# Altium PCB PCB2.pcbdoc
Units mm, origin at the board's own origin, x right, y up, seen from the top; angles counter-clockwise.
Board outline 115.73 x 193.8 mm, 2 copper layers (Top Layer, Bottom Layer); 58 components, 62 nets, 239 pads, 40 vias.
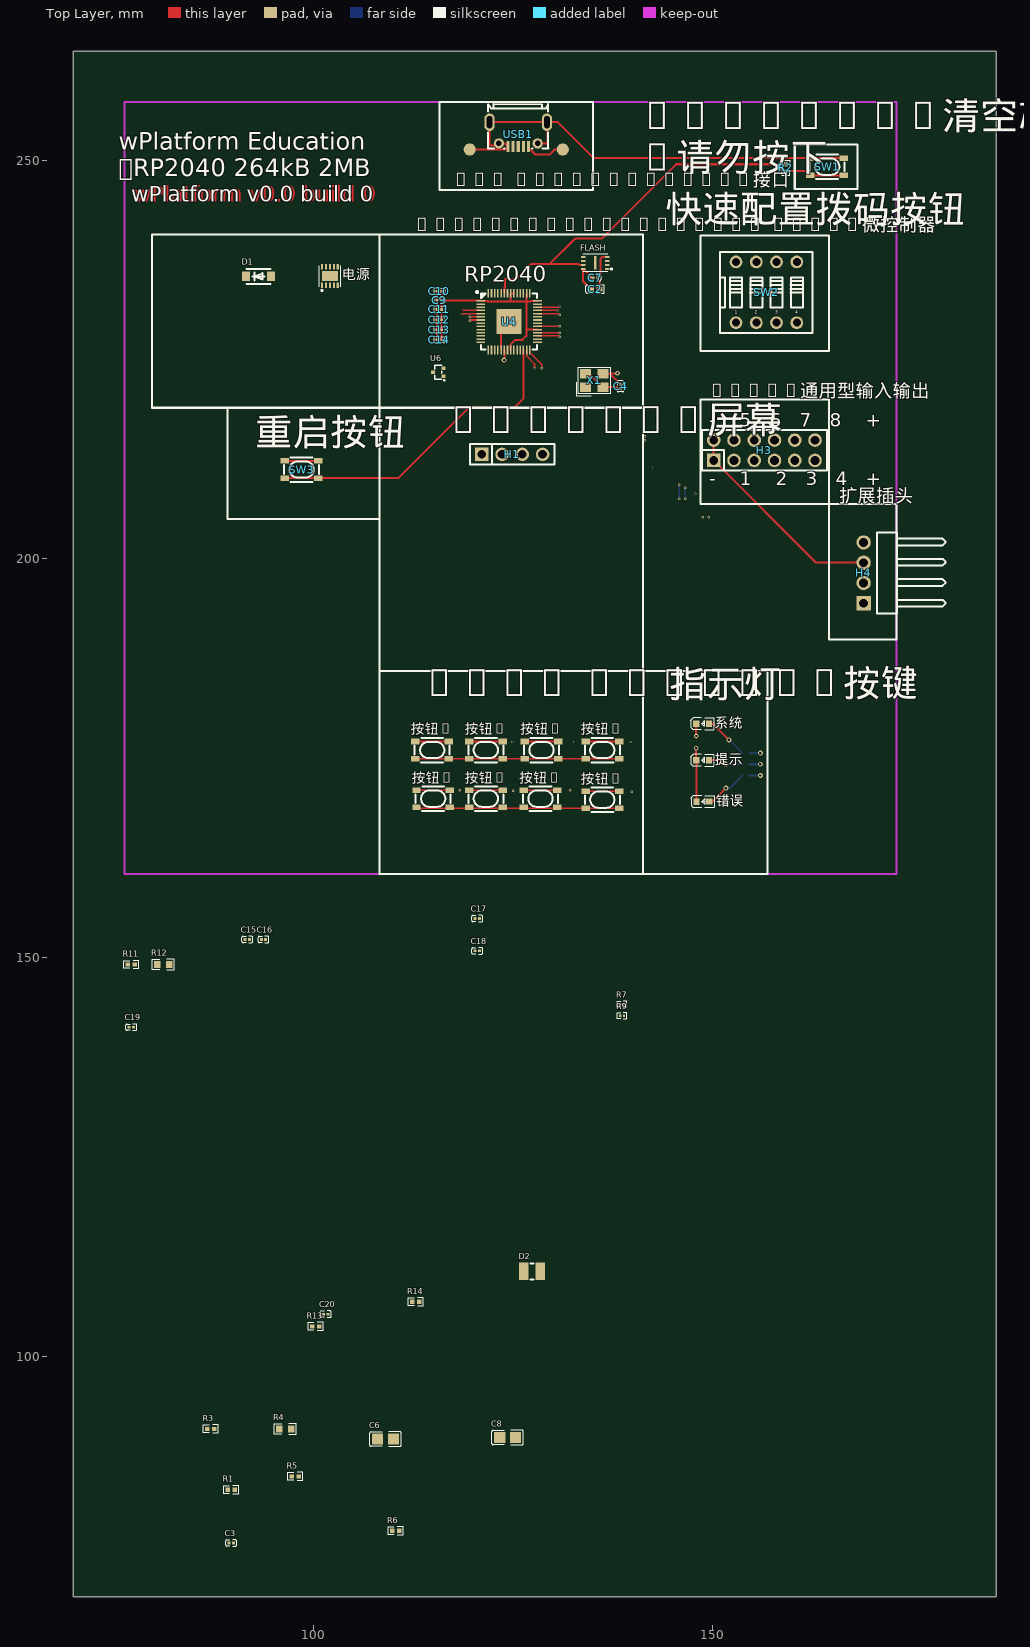
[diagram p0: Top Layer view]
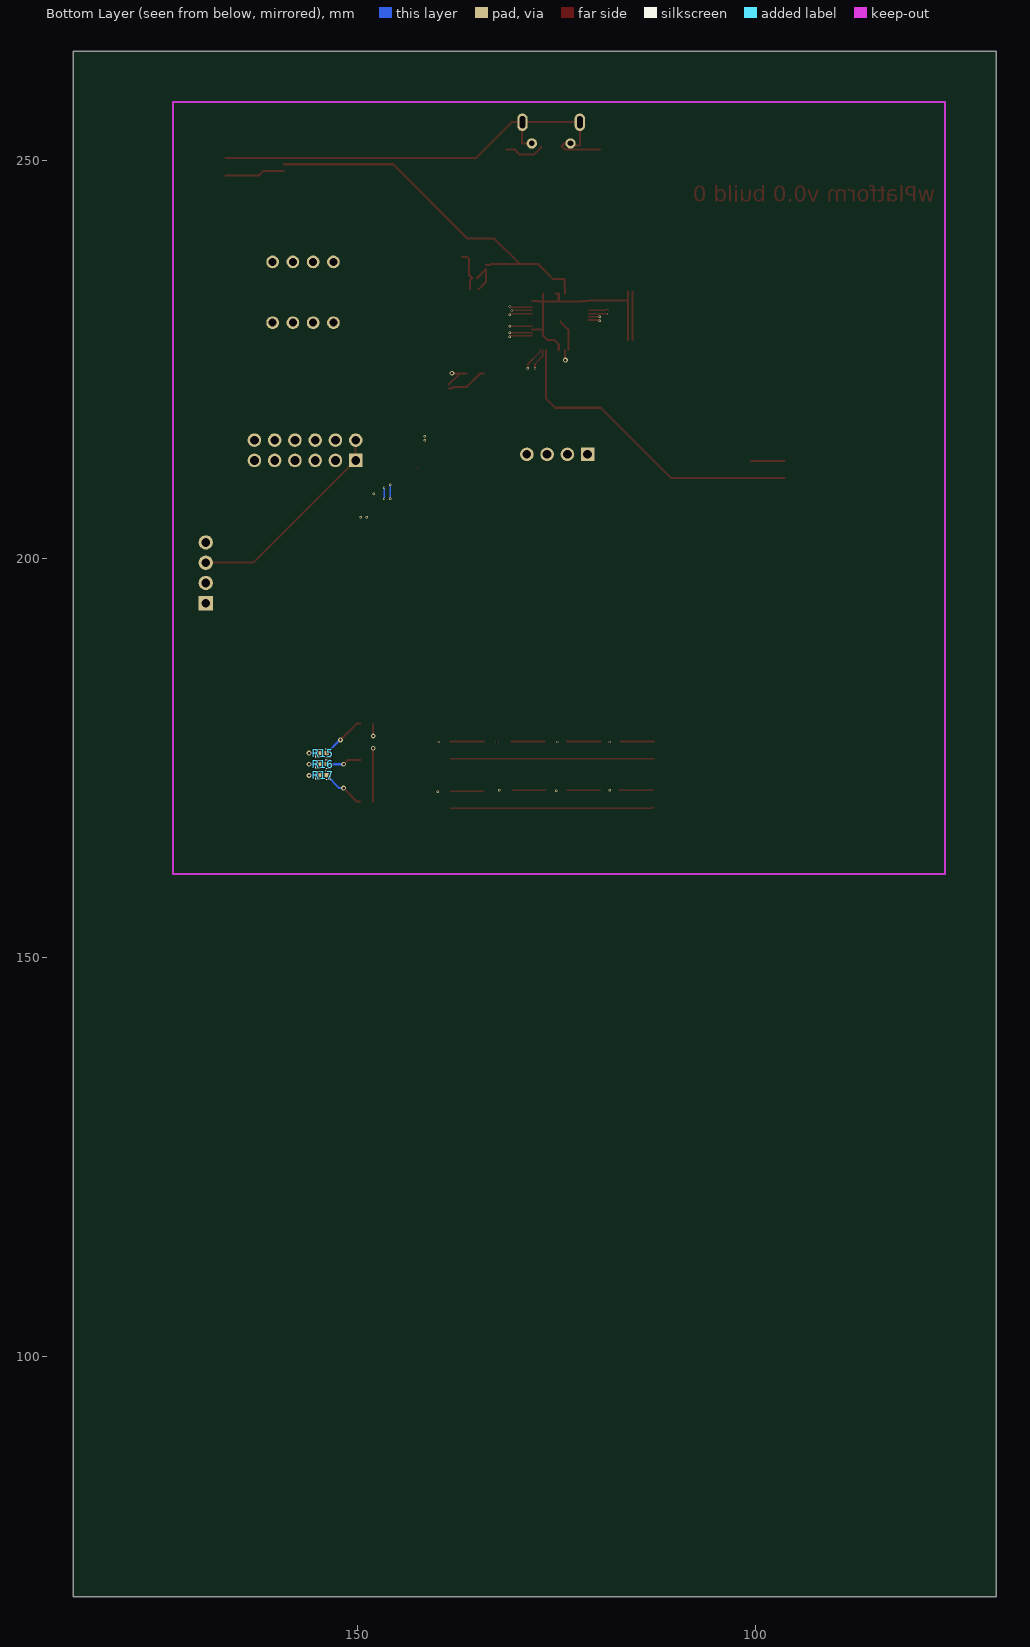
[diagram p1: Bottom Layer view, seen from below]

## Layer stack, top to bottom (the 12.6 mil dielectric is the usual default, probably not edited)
Top Layer: signal copper (thickness not stored)
Dielectric: dielectric 0.32, FR-4, Dk 4.8
Bottom Layer: signal copper (thickness not stored)

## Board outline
185.584,69.85 69.85,69.85 69.85,263.651 185.584,263.651

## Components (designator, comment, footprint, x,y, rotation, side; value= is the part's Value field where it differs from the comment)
C2 "CL05A225MQ5NSNC" C0402 135.298,233.823 r0 top
C3 "CL03C150JA3ANNC" C0201 89.655,76.591 r0 top
C4 "CL03C150JA3ANNC" C0201 138.481,221.614 r90 top
C6 "GRM21BR60J476ME01L" C0805 109.009,89.626 r0 top
C7 "GRM033R60J104KE19D" C0201 135.299,235.22 r180 top
C8 "GRM21BR60J476ME01L" C0805 124.32,89.816 r0 top
C9 "GRM033R60J104KE19D" C0201 115.748,232.409 r180 top
C10 "GRM033R60J104KE19D" C0201 115.748,233.552 r180 top
C11 "GRM033R60J104KE19D" C0201 115.748,231.266 r180 top
C12 "GRM033R60J104KE19D" C0201 115.748,229.996 r180 top
C13 "GRM033R60J104KE19D" C0201 115.748,228.726 r180 top
C14 "GRM033R60J104KE19D" C0201 115.748,227.456 r180 top
C15 "GRM033R60J104KE19D" C0201 91.682,152.268 r0 top
C16 "GRM033R60J104KE19D" C0201 93.708,152.268 r0 top
C17 "GRM033R60J104KE19D" C0201 120.509,154.897 r0 top
C18 "GRM033R60J104KE19D" C0201 120.509,150.834 r0 top
C19 "GRM033R60J104KE19D" C0201 77.144,141.267 r0 top
C20 "GRM033R71E102KA01D" C0201 101.514,105.293 r0 top
D1 "MBR120VLSFT1G" SOD-123F_L2.8-W1.8-LS3.7-RD 93.083,235.408 r0 top
D2 "SRN2512-2R2M" IND-SMD_L2.5-W2.0 127.396,110.644 r0 top
FLASH "W25Q16JVUXIQ" USON-8_L3.0-W2.0-P0.50-BL-EP 135.306,237.108 r90 top
H1 "2.54-1*4P母" HDR-TH_4P-P2.54-V-F 124.892,213.105 r0 top
H3 "B-2100S12P-B110" HDR-TH_12P-P2.54-V-M-R2-C6-S2.54 156.515,213.613 r0 top
H4 "2.54-1*4P反弯排针" HDR-TH_4P-P2.54-H-M-W10.4 168.961,198.246 r90 top
R1 "AECR0402F1K00K9" R0402 89.655,83.288 r0 top
R2 "AECR0402F1K00K9" R0402 159.182,249.046 r270 top
R3 "CR0402F5K60Q10Z" R0402 87.114,90.896 r0 top
R4 "0603WAF1002T5E" R0603 96.433,90.896 r0 top
R5 "RC0402FR-07100KL" R0402 97.703,84.937 r0 top
R6 "RC0402FR-07100KL" R0402 110.279,78.132 r0 top
R7 "RC0201FR-0727RL" R0201 138.667,144.134 r0 top
R9 "RC0201FR-0727RL" R0201 138.667,142.701 r0 top
R11 "RC0402FR-071RL" R0402 77.144,149.131 r0 top
R12 "RC0603FR-07200RL" R0603 81.139,149.131 r0 top
R13 "RC0402FR-07100KL" R0402 100.244,103.751 r0 top
R14 "RC0402FR-07200KL" R0402 112.82,106.835 r0 top
R15 "RC0402FR-07470RL" R0402 154.229,175.64 r180 bottom
R16 "RC0402FR-07470RL" R0402 154.229,174.243 r180 bottom
R17 "RC0402FR-07470RL" R0402 154.229,172.846 r180 bottom
SW1 "SKRPACE010" KEY-SMD_4P-L4.2-W3.2-P2.20-LS4.6 164.389,249.173 r0 top
SW2 "DS-04RP_C319060" SW-TH_DS-04XP 156.769,233.425 r0 top
SW3 "SKRPACE010" KEY-SMD_4P-L4.2-W3.2-P2.20-LS4.6 98.476,211.2 r0 top
U4 "RP2040_C2040" LQFN-56_L7.0-W7.0-P0.4-EP 124.503,229.749 r0 top
U6 "DMG1012T-13" SOT-523-3_L1.6-W0.8-P1.00-LS1.6-BR 115.621,223.392 r0 top
USB1 "MicroXNJ" MICRO-USB-SMD_MICROXNJ 125.654,253.237 r180 top
X1 "X322512MMB4SI" CRYSTAL-SMD_4P-L3.2-W2.5-BL 135.179,222.376 r0 top
按钮1 "SKRPACE010" KEY-SMD_4P-L4.2-W3.2-P2.20-LS4.6 114.859,176.021 r0 top
按钮2 "SKRPACE010" KEY-SMD_4P-L4.2-W3.2-P2.20-LS4.6 121.59,176.021 r0 top
按钮3 "SKRPACE010" KEY-SMD_4P-L4.2-W3.2-P2.20-LS4.6 128.575,176.021 r0 top
按钮4 "SKRPACE010" KEY-SMD_4P-L4.2-W3.2-P2.20-LS4.6 136.195,176.021 r0 top
按钮5 "SKRPACE010" KEY-SMD_4P-L4.2-W3.2-P2.20-LS4.6 114.986,169.925 r0 top
按钮6 "SKRPACE010" KEY-SMD_4P-L4.2-W3.2-P2.20-LS4.6 121.59,169.925 r0 top
按钮7 "SKRPACE010" KEY-SMD_4P-L4.2-W3.2-P2.20-LS4.6 128.448,169.925 r0 top
按钮8 "SKRPACE010" KEY-SMD_4P-L4.2-W3.2-P2.20-LS4.6 136.195,169.798 r0 top
提示 "19-217/GHC-YR1S2/3T" LED0603-RD 148.768,174.751 r0 top
电源 "RT6150BGQW" WSON-10_L2.5-W2.5-P0.50-BL-EP 102.032,235.457 r0 top
系统 "19-217/GHC-YR1S2/3T" LED0603-RD 148.768,179.323 r0 top
错误 "NCD0603R1_C84263" LED0603-RD_RED 148.81,169.563 r0 top

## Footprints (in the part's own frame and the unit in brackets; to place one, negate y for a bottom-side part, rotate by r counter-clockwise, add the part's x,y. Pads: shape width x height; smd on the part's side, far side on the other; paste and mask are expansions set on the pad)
C0201 [mm]
  rect 0.368x0.324 smd paste-100 mask+0.051: 1(-0.274,0) 2(0.274,0)
  silkscreen extent -0.69,-0.39 0.69,0.39
C0402 [mm]
  rect 0.79x0.54 smd paste-100 mask+0.051: 1(-0.545,0) 2(0.545,0)
  silkscreen extent -1.17,-0.5 1.17,0.5
C0805 [mm]
  rect 1.41x1.35 smd paste-100 mask+0.051: 1(-1,0) 2(1,0)
  silkscreen extent -1.96,-0.9 1.96,0.9
CRYSTAL-SMD_4P-L3.2-W2.5-BL [mm]
  rect 1.4x1.2 smd paste+0 mask+0.051: 1(-1.1,-0.85) 2(1.1,-0.85) 3(1.1,0.85) 4(-1.1,0.85)
  silkscreen extent -2.26,-1.91 2.03,1.68
HDR-TH_4P-P2.54-H-M-W10.4 [mm]
  rect 1.8x1.8 hole 1.1 mask+0.051: 1(-3.81,0)
  round 1.8 hole 1.1 mask+0.051: 2(-1.27,0) 3(1.27,0) 4(3.81,0)
  silkscreen extent -5.09,-10.27 5.07,-1.65
HDR-TH_4P-P2.54-V-F [mm]
  rect 1.7x1.7 hole 1.1 mask+0.051: 1(-3.81,0)
  round 1.7 hole 1.1 mask+0.051: 2(-1.27,0) 3(1.27,0) 4(3.81,0)
  silkscreen extent -5.29,-1.27 5.29,1.27
HDR-TH_12P-P2.54-V-M-R2-C6-S2.54 [mm]
  rect 1.7x1.7 hole 1.1 mask+0.051: 1(-6.35,-1.27)
  round 1.7 hole 1.1 mask+0.051: 2(-6.35,1.27) 3(-3.81,-1.27) 4(-3.81,1.27) 5(-1.27,-1.27) 6(-1.27,1.27) 7(1.27,-1.27) 8(1.27,1.27) 9(3.81,-1.27) 10(3.81,1.27) 11(6.35,-1.27) 12(6.35,1.27)
  silkscreen extent -7.85,-2.54 7.85,2.54
IND-SMD_L2.5-W2.0 [mm]
  rect 1.2x2.2 smd paste+0 mask+0.051: 1(1.028,0) 2(-1.028,0)
  silkscreen extent -0.2,-1.02 0.2,1.02
KEY-SMD_4P-L4.2-W3.2-P2.20-LS4.6 [mm]
  rect 1.05x0.7 smd mask+0.051: 1(-2.1,1.075) 2(2.1,1.075) 3(-2.1,-1.075) 4(2.1,-1.075)
  silkscreen extent -2.2,-1.55 2.2,1.52
LED0603-RD [mm]
  rect 0.8x0.8 smd paste+0 mask+0.051: 1(-0.799,-0.003) 2(0.799,0.003)
  silkscreen extent -1.49,-0.75 1.39,0.76
LED0603-RD_RED [mm]
  rect 0.8x0.8 smd mask+0.051: 1(-0.8,-0.003) 2(0.8,0.003)
  silkscreen extent -1.49,-0.75 1.39,0.76
LQFN-56_L7.0-W7.0-P0.4-EP [mm]
  rect 1.1x0.2 smd paste-100 mask+0.05: 1(-3.55,2.6) 2(-3.55,2.2) 3(-3.55,1.8) 4(-3.55,1.4) 5(-3.55,1) 6(-3.55,0.6) 7(-3.55,0.2) 8(-3.55,-0.2) 9(-3.55,-0.6) 10(-3.55,-1) 11(-3.55,-1.4) 12(-3.55,-1.8) 13(-3.55,-2.2) 14(-3.55,-2.6) 29(3.55,-2.6) 30(3.55,-2.2) 31(3.55,-1.8) 32(3.55,-1.4) 33(3.55,-1) 34(3.55,-0.6) 35(3.55,-0.2) 36(3.55,0.2) 37(3.55,0.6) 38(3.55,1) 39(3.55,1.4) 40(3.55,1.8) 41(3.55,2.2) 42(3.55,2.6)
  rect 0.2x1.1 smd paste-100 mask+0.05: 15(-2.6,-3.55) 16(-2.2,-3.55) 17(-1.8,-3.55) 18(-1.4,-3.55) 19(-1,-3.55) 20(-0.6,-3.55) 21(-0.2,-3.55) 22(0.2,-3.55) 23(0.6,-3.55) 24(1,-3.55) 25(1.4,-3.55) 26(1.8,-3.55) 27(2.2,-3.55) 28(2.6,-3.55) 43(2.6,3.55) 44(2.2,3.55) 45(1.8,3.55) 46(1.4,3.55) 47(1,3.55) 48(0.6,3.55) 49(0.2,3.55) 50(-0.2,3.55) 51(-0.6,3.55) 52(-1,3.55) 53(-1.4,3.55) 54(-1.8,3.55) 55(-2.2,3.55) 56(-2.6,3.55)
  rect 3.1x3.1 smd paste-100 mask+0.05: 57(0,0)
  silkscreen extent -4.13,-3.5 3.5,3.83
MICRO-USB-SMD_MICROXNJ [mm]
  rect 0.4x1.4 smd paste-100 mask+0.051: 1(-1.3,1.521) 2(-0.65,1.521) 3(0,1.521) 4(0.65,1.521) 5(1.3,1.521)
  round 1.3 hole 0.7 mask+0.051: 6(2.425,1.149) 9(-2.425,1.149)
  oval 1.3x2.2 hole 0.7 slot 1.5 at 90 deg mask+0.051: 7(3.6,-1.521) 8(-3.6,-1.521)
  silkscreen extent -3.76,-3.78 3.8,1.79
R0201 [mm]
  rect 0.303x0.324 smd paste-100 mask+0.051: 1(-0.242,0) 2(0.242,0)
  silkscreen extent -0.62,-0.39 0.62,0.39
R0402 [mm]
  rect 0.566x0.54 smd paste-100 mask+0.051: 1(-0.433,0) 2(0.433,0)
  silkscreen extent -0.94,-0.5 0.94,0.5
R0603 [mm]
  rect 0.806x0.864 smd paste-100 mask+0.051: 1(-0.753,0) 2(0.753,0)
  silkscreen extent -1.39,-0.66 1.39,0.66
SOD-123F_L2.8-W1.8-LS3.7-RD [mm]
  rect 1x1.2 smd paste+0 mask+0.051: 1(-1.55,0) 2(1.55,0)
  silkscreen extent -1.52,-0.93 1.49,0.95
SOT-523-3_L1.6-W0.8-P1.00-LS1.6-BR [mm]
  rect 0.51x0.4 smd paste+0 mask+0.051: 1(0.65,-0.5) 2(0.65,0.5) 3(-0.65,0)
  silkscreen extent -0.45,-1.08 0.83,0.9
SW-TH_DS-04XP [mm]
  round 1.6 hole 1 mask+0.051: 1(-3.81,-3.81) 2(-1.27,-3.81) 3(1.27,-3.81) 4(3.81,-3.81) 5(3.81,3.81) 6(1.27,3.81) 7(-1.27,3.81) 8(-3.81,3.81)
  silkscreen extent -5.83,-5.11 5.79,5.05
USON-8_L3.0-W2.0-P0.50-BL-EP [mm]
  rect 0.28x0.6 smd paste+0 mask+0.051: 1(-0.75,-1.507) 2(-0.25,-1.507) 3(0.25,-1.507) 4(0.75,-1.507) 5(0.75,1.507) 6(0.25,1.507) 7(-0.25,1.507) 8(-0.75,1.507)
  rect 1.7x0.3 smd paste+0 mask+0.051: 9(0,0)
  silkscreen extent -1.08,-2.13 1.08,1.58
WSON-10_L2.5-W2.5-P0.50-BL-EP [mm]
  rect 0.28x0.665 smd paste+0 mask+0.051: 1(-1,-1.157) 2(-0.5,-1.157) 3(0,-1.157) 4(0.5,-1.157) 5(1,-1.157) 6(1,1.157) 7(0.5,1.157) 8(0,1.157) 9(-0.5,1.157) 10(-1,1.157)
  rect 2x1.25 smd paste+0 mask+0.051: 11(0,0)
  silkscreen extent -1.33,-1.89 1.33,1.33

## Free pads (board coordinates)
  round 1.524 smd mask+0.051: 1(131.242,251.332) 2(119.558,251.332)

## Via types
v1: diameter 0.3, hole 0.2, Top Layer to Bottom Layer, 28 vias
v2: diameter 0.61, hole 0.305, Top Layer to Bottom Layer, 10 vias
v3: diameter 0.2, hole 0.15, Top Layer to Bottom Layer, 2 vias

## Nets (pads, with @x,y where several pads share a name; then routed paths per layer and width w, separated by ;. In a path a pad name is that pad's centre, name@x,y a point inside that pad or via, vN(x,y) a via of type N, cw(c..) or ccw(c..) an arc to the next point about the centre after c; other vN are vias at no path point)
0GPIO23: R6.2 U4.35 电源.7
0GPIO24: R3.1 R4.1 U4.36
0USB0: R7.1 U4.47
0USB1: R9.1 U4.46
1V10: C15.2 C16.1 C18.2 U4.23 U4.45 U4.50
$1N2633: C6.2 D1.1 R5.2 R14.2 电源.5 电源.8
$1N2647: R5.1 电源.6
$1N2652: D2.1 电源.4
$1N2653: D2.2 电源.2
$1N2694: C3.2 R1.1 X1.1
$1N2712: SW2.1 U4.8
$1N2715: SW2.2 U4.9
$1N2718: SW2.3 U4.11
$1N2721: SW2.4 U4.12
$1N2886: R11.2 R12.2 U4.43
$1N2892: C19.2 R11.1
$1N2897: U4.41 U6.2
$1N2936: C20.2 R13.2 R14.1 U6.3
$1N3176: R2.2 SW1.3 SW1.4 | length 7.5
  Top Layer w0.254: R2.2 161.774,248.613 SW1.3 SW1.4
$1N4076: R7.2 USB1.3
$1N4082: R9.2 USB1.2
$1N6993: R15.2 系统.2 | length 5.8
  Top Layer w0.254: 系统.2 150.034,179.326 v2(152.07,177.291)
  Bottom Layer w0.254: v2(152.07,177.291) 152.081,177.302 152.134,177.302 R15.2
$1N7116: R16.2 提示.2 | length 4.4
  Top Layer w0.254: 提示.2 151.177,174.754 v2(151.689,174.243)
  Bottom Layer w0.254: v2(151.689,174.243) R16.2
$1N7152: R17.2 错误.2 | length 5.5
  Top Layer w0.254: 错误.2 150,169.567 v2(151.689,171.256)
  Bottom Layer w0.254: v2(151.689,171.256) 152.206,171.256 R17.2
BOOTSEL_TO_EEPROM: FLASH.7 R2.1 U4.51 | length 47.2
  Top Layer w0.254: U4.51 123.903,234.026 124.003,234.126 124.003,235.076 125.4,235.076 127.305,236.981 129.591,236.981 ; FLASH.7 133.321,236.858 133.198,236.981 129.591,236.981 ; R2.1 145.466,249.479 136.143,240.156 132.766,240.156 129.591,236.981
EPCLK0: FLASH.6 U4.52
EPSD00: FLASH.5 U4.53
EPSD10: FLASH.2 U4.55
EPSD20: FLASH.3 U4.54
EPSS0: FLASH.1 U4.56
GND: C2.2 C3.1 C4.1 C6.1 C7.1 C8.2 C9.2 C10.2 C11.2 C12.2 C13.2 C14.2 C15.1 C16.2 C17.1 C18.1 C19.1 C20.1 FLASH.4 H1.1 H3.1 H3.2 H4.3 pad.2 R4.2 R6.1 R13.1 SW1.1 SW1.2 SW3.1 SW3.2 U4.19 U4.57 USB1.5 USB1.6 USB1.7 USB1.8 USB1.9 X1.2 X1.4 提示.1 电源.3 电源.9 电源.11 系统.1 错误.1 | length 121.5
  Top Layer w0.254: SW3.1 SW3.2 ; C14.2 C13.2 C12.2 C11.2 C9.2 C10.2 ; pad.2 123.97,251.332 USB1.5 123.981,252.088 USB1.6 122.981,251.84 122.054,251.84 USB1.7 USB1.8 USB1.8@129.337,254.675 ; U4.19 123.503,228.749 U4.57 ; USB1.9 129.337,252.088 USB1.8@129.337,254.675 ; X1.4 134.579,223.226 X1.2 137.955,221.526 138.141,221.34 C4.1 ; C2.2 135.843,234.951 C7.1 135.941,235.588 135.941,237.616 136.183,237.858 FLASH.4 ; v2(147.968,176.246) 提示.1 148.011,174.705 错误.1 ; v2(147.968,177.787) 系统.1 ; H3.2 H3.1 162.992,199.516 H4.3 ; SW1.2 SW1.1 135.12,250.248 130.607,254.761 129.423,254.761 USB1.8@129.337,254.675
  Inner1 w0.254: v2(147.968,176.246) v2(147.968,177.787)
GP0: H3.3 U4.31 | length 42.5
  Top Layer w0.2: U4.31 130.749,227.949 v1(130.861,227.837)
  Inner2 w0.2: v1(130.861,227.837) 131.75,226.948 135.052,226.948 136.195,225.805 139.37,225.805 142.037,223.138 142.037,209.295 142.926,208.406 146.736,208.406 147.371,209.041 149.403,209.041 H3.3
GP1: H3.5 U4.32 | length 45.1
  Top Layer w0.2: U4.32 130.853,228.349 v1(130.861,228.341)
  Inner1 w0.2: v1(142.418,211.454) 142.418,209.93 144.196,208.152 v1(147.879,208.152)
  Inner2 w0.2: v1(130.861,228.341) 130.992,228.341 132.004,227.329 135.179,227.329 136.322,226.186 139.57,226.186 142.418,223.338 v1(142.418,211.454) ; v1(147.879,208.152) 150.673,208.152 154.864,212.343 H3.5
GP2: H3.7 U4.34 | length 49.6
  Top Layer w0.2: U4.34 130.856,229.149 v1(130.861,229.144)
  Inner2 w0.2: v1(130.861,229.144) 132.295,227.71 135.306,227.71 136.449,226.567 139.751,226.567 142.799,223.519 142.799,211.781 143.053,211.527 143.053,211.327 142.799,211.073 142.799,210.057 143.942,208.914 v1(146.609,208.914) ; v1(146.609,207.517) 147.879,207.517 148.133,207.771 153.213,207.771 H3.7
  Bottom Layer w0.2: v1(146.609,207.517) v1(146.609,208.914)
GP3: H3.9 U4.5 | length 65.4
  Top Layer w0.2: v3(118.542,230.758) 120.944,230.758 U4.5
  Inner2 w0.2: v3(118.542,230.758) 126.67,230.758 127.813,229.615 130.988,229.615 132.385,228.218 135.052,228.218 135.258,228.012 135.431,228.012 136.574,226.869 139.876,226.869 143.101,223.644 143.101,211.914 143.688,211.327 143.307,210.946 143.307,210.184 144.196,209.295 v1(145.847,209.295) ; v1(145.847,207.517) 146.355,207.009 146.863,207.009 146.99,207.136 148.26,207.136 148.514,207.39 155.372,207.39 H3.9
  Bottom Layer w0.2: v1(145.847,207.517) v1(145.847,209.295)
GP4: H3.4 U4.38 | length 31.2
  Top Layer w0.2: U4.38 130.743,230.749 v1(130.861,230.631)
  Inner2 w0.2: v1(130.861,230.631) 132.893,228.599 135.306,228.599 136.703,227.202 140.386,227.202 H3.4
GP5: H3.6 U4.39 | length 33.9
  Top Layer w0.2: U4.39 130.607,231.149 v1(130.607,231.139)
  Inner2 w0.2: v1(130.607,231.139) 131.242,231.139 133.401,228.98 135.56,228.98 136.957,227.583 140.513,227.583 152.07,216.026 154.102,216.026 H3.6
GP6: H3.8 U4.40 | length 36.7
  Top Layer w0.2: U4.40 130.763,231.549 v1(130.861,231.647)
  Inner2 w0.2: v1(130.861,231.647) 131.242,231.647 133.528,229.361 135.687,229.361 137.084,227.964 140.64,227.964 152.197,216.407 156.261,216.407 H3.8
GP7: H3.10 U4.4 | length 51.8
  Top Layer w0.2: v3(118.574,231.149) U4.4
  Inner2 w0.2: v3(118.574,231.149) 129.22,231.149 130.353,232.282 131.623,232.282 134.163,229.742 135.814,229.742 137.211,228.345 140.767,228.345 152.324,216.788 158.42,216.788 H3.10
IOVDD00: C2.1 C7.2 C8.1 C9.1 C10.1 C11.1 C12.1 C13.1 C14.1 C17.2 FLASH.8 H1.2 H3.11 H3.12 R12.1 SW2.5 SW2.6 SW2.7 SW2.8 U4.1 U4.10 U4.22 U4.33 U4.42 U4.44 U4.48 U4.49 U6.1 按钮1.3 按钮1.4 按钮2.3 按钮2.4 按钮3.3 按钮3.4 按钮4.3 按钮4.4 按钮5.3 按钮5.4 按钮6.3 按钮6.4 按钮7.3 按钮7.4 按钮8.3 按钮8.4 电源.1 电源.10 | length 95.3
  Top Layer w0.2: 按钮1.3 按钮1.4 按钮2.3 按钮2.4 按钮3.3 按钮3.4 按钮4.3 按钮4.4 ; 按钮5.3 113.013,168.723 按钮8.3 按钮8.4
  Top Layer w0.254: C14.1 C13.1 C12.1 C11.1 C9.1 ; C10.1 C9.1 ; U4.22 124.703,226.886 125.273,227.456 126.162,227.456 126.67,227.964 126.67,228.622 ; U4.48 U4.49 124.703,232.282 ; U4.44 126.703,232.282 ; U4.33 126.797,228.749 126.67,228.622 ; U4.42 127.326,232.349 127.259,232.282 126.703,232.282 ; C2.1 133.798,234.778 FLASH.8 134.936,235.22 C7.2 ; C9.1 120.893,232.409 U4.1 121.68,232.349 121.747,232.282 124.703,232.282 ; 124.703,232.282 126.703,232.282 ; 126.67,228.622 126.67,232.249 126.703,232.282
  Inner1 w0.254: SW2.8 SW2.7 SW2.6 SW2.5
  Inner2 w0.2: H3.11 H3.12
LED0: R16.1 U4.2 | length 5.1
  Inner2 w0.254: v2(156.007,174.245) 156.515,174.245 156.642,174.372 156.642,177.418
  Bottom Layer w0.254: R16.1 156.005,174.243 v2(156.007,174.245)
LED1: R17.1 U4.3 | length 6.5
  Inner2 w0.254: v2(156.007,172.836) 157.277,174.106 157.277,177.418
  Bottom Layer w0.254: R17.1 155.997,172.846 v2(156.007,172.836)
OBLED: R15.1 U4.37 | length 3.1
  Inner2 w0.254: v2(156.007,175.64) 156.007,177.418
  Bottom Layer w0.254: R15.1 v2(156.007,175.64)
RUN: SW3.3 SW3.4 U4.26 | length 40.2
  Top Layer w0.254: SW3.3 SW3.4 110.609,210.125 119.431,218.947 125.146,218.947 126.289,220.09 126.289,226.185 U4.26
SCL: H1.3 U4.6 | length 24.8
  Top Layer w0.2: v1(119.558,230.377) 120.925,230.377 U4.6
  Inner1 w0.2: v1(119.558,230.377) 119.308,230.377 118.415,229.484 118.415,228.726 118.288,228.599 118.288,217.296 120.828,214.756 124.511,214.756 H1.3
SDA: H1.4 U4.7 | length 25.8
  Top Layer w0.2: v1(119.558,229.869) 119.638,229.949 U4.7
  Inner1 w0.2: v1(119.558,229.869) 118.796,229.107 118.796,217.55 121.209,215.137 126.67,215.137 H1.4
SWCLK: U4.24
SWD: U4.25
UARTRX: H4.2 U4.28 | length 56.8
  Top Layer w0.2: U4.28 127.103,225.88 128.575,224.408 v1(128.575,223.9)
  Inner1 w0.2: v1(141.529,215.391) 143.688,215.391 149.53,209.549 v1(149.53,205.231)
  Inner2 w0.2: v1(128.575,223.9) 137.084,215.391 141.377,215.391 ; v1(149.53,205.231) 157.785,196.976 H4.2
UARTTX: H4.1 U4.27 | length 58.7
  Top Layer w0.2: U4.27 126.703,225.424 127.686,224.441 v1(127.686,223.9)
  Inner1 w0.2: v1(141.529,214.883) 143.434,214.883 148.768,209.549 v1(148.768,205.231)
  Inner2 w0.2: v1(127.686,223.9) 136.576,215.01 141.152,215.01 141.279,214.883 v1(141.529,214.883) ; v1(148.768,205.231) 157.404,196.595 166.802,196.595 H4.1
UB0: U4.13 按钮1.1 按钮1.2 | length 4.2
  Top Layer w0.2: 按钮1.1 按钮1.2
  other v1: 118.288,177.037
UB1: U4.14 按钮5.1 按钮5.2 | length 4.2
  Top Layer w0.2: 按钮5.1 按钮5.2
UB2: U4.15 按钮2.1 按钮2.2 | length 4.2
  Top Layer w0.254: 按钮2.1 按钮2.2
  other v1: 124.892,177.037
UB3: U4.16 按钮6.1 按钮6.2 | length 4.2
  Top Layer w0.2: 按钮6.1 按钮6.2
UB4: U4.17 按钮3.1 按钮3.2 | length 4.2
  Top Layer w0.2: 按钮3.1 按钮3.2
  other v1: 132.512,177.037
UB5: U4.18 按钮7.1 按钮7.2 | length 4.2
  Top Layer w0.2: 按钮7.1 按钮7.2
  other v1: 118.296,171
UB6: U4.29 按钮4.1 按钮4.2 | length 4.2
  Top Layer w0.254: 按钮4.1 按钮4.2
  other v1: 125.019,170.941 139.751,177.037
UB7: U4.30 按钮8.1 按钮8.2 | length 4.2
  Top Layer w0.2: 按钮8.1 按钮8.2
VCC: D1.2 H4.4 pad.1 R3.2 USB1.1 | length 5.1
  Top Layer w0.254: USB1.1 126.954,251.556 127.813,250.697 129.591,250.697 130.226,251.332 pad.1
XIN0: C4.2 U4.20 X1.3 | length 20.3
  Top Layer w0.254: v2@123.903,224.916 U4.20 ; X1.3 137.143,223.226 ; v2@138.1,223.226 137.143,223.226 ; C4.2 137.143,223.226
  Inner1 w0.254: v2(123.876,224.916) 137.084,224.916 138.1,223.9 v2(138.1,223.265)
XOUT0: R1.2 U4.21
"": FLASH.9 USB1.4
  other v1: 139.878,170.814 132.164,171

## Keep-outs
Board Outline Layer:
  lines w0.254 net "": 76.251,160.491 173.061,160.491 173.061,257.301 76.251,257.301 76.251,160.491

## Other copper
Top Layer:
  text "wPlatform v0.0 build 0" at 77.479,244.77 h1.98

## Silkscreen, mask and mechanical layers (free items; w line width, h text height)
Top Silkscreen Layer:
  lines w0.254 net "": 108.255,185.927 141.275,185.927 ; 108.255,185.927 108.255,218.947 ; 108.255,185.927 141.275,185.927 ; 108.255,185.927 108.255,160.491 141.275,160.491 ; 108.255,218.947 141.275,218.947 ; 108.255,218.947 108.255,240.664 ; 108.255,218.947 141.275,218.947 ; 108.255,218.947 79.728,218.947 79.728,240.664 108.255,240.664 ; 108.255,218.947 108.255,240.664 ; 108.255,218.947 108.255,204.977 89.205,204.977 89.205,218.947 108.255,218.947 ; 108.255,240.664 141.275,240.664 141.275,218.947 ; 141.275,160.491 141.275,185.927 ; 141.275,160.491 156.916,160.491 156.916,185.927 141.275,185.927 ; 141.275,160.491 141.275,185.927 ; 141.275,185.927 141.275,218.947 ; 164.643,206.882 148.514,206.882 148.514,219.963 164.643,219.963 164.643,206.882 ; 164.643,206.882 173.061,206.882 173.061,189.864 164.643,189.864 164.643,206.882 ; 115.806,246.252 135.052,246.252 135.052,257.301 115.806,257.301 115.806,246.252 ; 148.514,226.059 164.643,226.059 164.643,240.537 148.514,240.537 148.514,226.059 ; 160.325,246.379 168.199,246.379 168.199,251.967 160.325,251.967 160.325,246.379
  text "BOOTSEL/清空芯片 /  请勿按下" at 140.706,248.638 h3.49
  text "wPlatform Education /  RP2040 264kB 2MB" at 75.571,247.978 h2.21
  text "USB Interface/USB接口" at 117.341,246.692 h1.7
  text "wPlatform v0.0 build 0" at 77.118,244.77 h1.98
  text "快速配置拨码按钮" at 144.116,242.19 h3.45
  text "MCU/Microcontroller Unit/微控制器" at 112.431,241.104 h1.7
  text "RP2040" at 118.874,234.737 h1.98
  text "GPIO/通用型输入输出" at 149.443,220.276 h1.7
  text "-    5   6   7   8    +" at 149.616,216.593 h1.7
  text "Screen/屏幕" at 116.438,215.774 h3.45
  text "重启按钮" at 92.646,214.25 h3.45
  text "-    1    2   3   4   +" at 149.616,209.227 h1.7
  text "扩展插头" at 165.919,207.068 h1.7
  text "User button/按键" at 113.433,182.754 h3.45
  text "指示灯" at 144.581,182.627 h3.45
